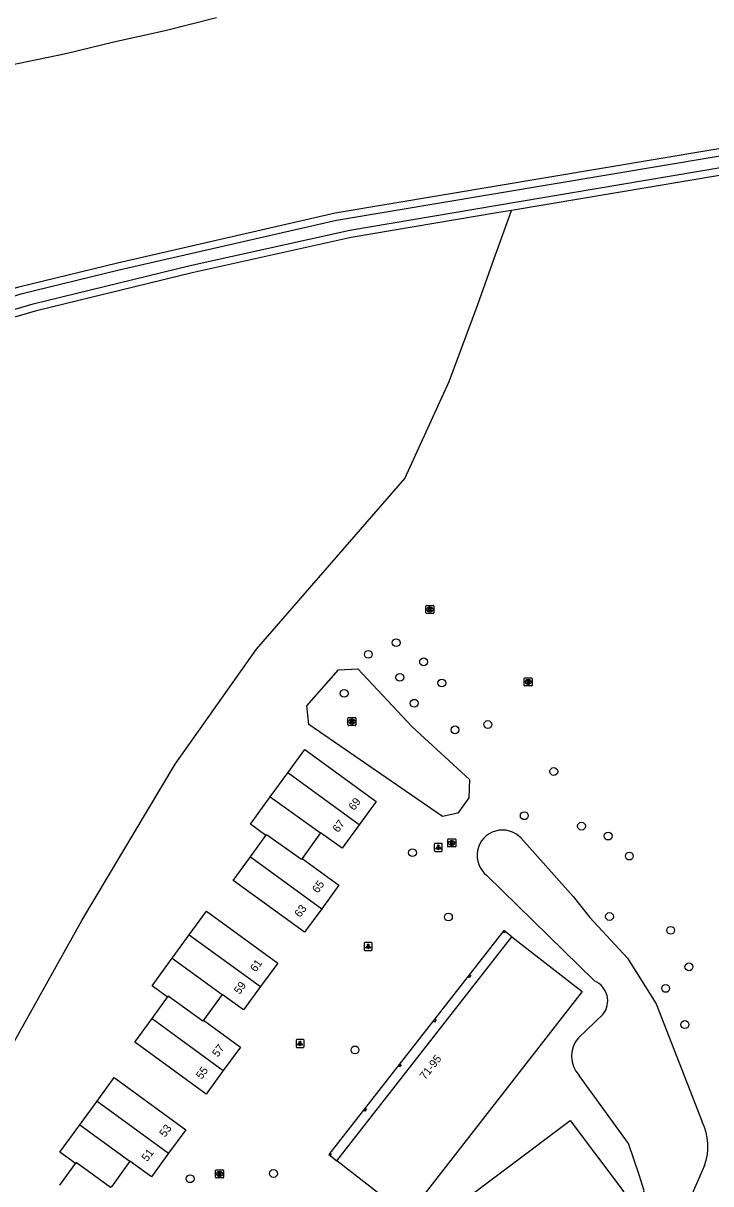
# Model space of a CAD drawing. Extents: x 159451 to 160663, y 388402 to 389723.
# Drawn here: x 159537.5 to 159623.4, y 389378.7 to 389523.7 of the extents above; entities that cross this region are included whole.
import ezdxf

# ---------------------------------------------------------------- set-up
doc = ezdxf.new("R2010")
doc.units = 0
for name, color, linetype in [('IMGEO_Boom', 7, 'Continuous'), ('IMGEO_Greppel_droge_sloot', 7, 'Continuous'), ('IMGEO_Groenvoorziening', 7, 'Continuous'), ('IMGEO_Lichtpunt', 7, 'Continuous'), ('IMGEO_Loofbos', 7, 'Continuous'), ('IMGEO_Meer_plas_ven_vijver', 7, 'Continuous'), ('IMGEO_Pand', 7, 'Continuous'), ('IMGEO_Pand_nummerreeks', 7, 'Continuous'), ('IMGEO_Pand_overbouw', 7, 'Continuous'), ('IMGEO_Rioolput', 7, 'Continuous')]:
    doc.layers.add(name, color=color, linetype=linetype)

msp = doc.modelspace()

# ---------------------------------------------------------------- linework, layer by layer
at = {"layer": 'IMGEO_Boom'}
for centre in [(159584.08, 389446.29), (159580.61, 389444.83), (159587.51, 389443.9), (159584.54, 389441.96), (159589.79, 389441.25), (159577.59, 389439.96), (159586.34, 389438.72), (159591.44, 389435.4), (159595.54, 389436.07), (159603.78, 389430.19), (159600.09, 389424.66), (159607.24, 389423.36), (159610.57, 389422.12), (159586.12, 389420.04), (159613.22, 389419.62), (159590.61, 389412), (159610.74, 389412.07), (159618.38, 389410.34), (159620.66, 389405.78), (159617.76, 389403.08), (159620.16, 389398.56), (159578.94, 389395.39), (159558.34, 389379.29), (159568.76, 389379.94)]:
    msp.add_circle(centre, 0.489, dxfattribs=at)
at = {"layer": 'IMGEO_Greppel_droge_sloot'}
for points in [[(159636.97, 389509.2), (159576.64, 389499.06), (159549.47, 389492.85), (159537.2, 389489.84), (159529.84, 389487.62), (159524.73, 389485.71), (159521.07, 389483.56), (159517.26, 389480.74), (159512.48, 389476.42), (159508.93, 389471.27), (159507.1, 389466.58), (159505.63, 389461.3), (159504.52, 389456.13), (159503.66, 389450.55), (159500.95, 389426.85), (159489.57, 389330.45)], [(159490.64, 389330.24), (159499.05, 389400.46), (159504.98, 389451.19), (159506.87, 389461.63), (159508.71, 389466.85), (159510.07, 389470.22), (159513.86, 389475.84), (159519.24, 389480.5), (159524.71, 389483.94), (159529.91, 389486.08), (159538.73, 389488.65), (159558.36, 389493.45), (159578.28, 389497.87), (159596.51, 389500.94), (159637.44, 389507.84)]]:
    msp.add_lwpolyline(points, dxfattribs=at)
at = {"layer": 'IMGEO_Groenvoorziening'}
msp.add_lwpolyline([(159688.02, 389515.39), (159637.6, 389506.89), (159598.51, 389500.31)], dxfattribs=at)
at = {"layer": 'IMGEO_Lichtpunt'}
for p, q in [((159589.75, 389421.21), (159588.95, 389421.21)), ((159589.75, 389421.21), (159588.95, 389421.21)), ((159588.85, 389421.11), (159588.85, 389420.3)), ((159588.85, 389421.11), (159588.85, 389420.3)), ((159588.95, 389420.21), (159589.75, 389420.21)), ((159588.95, 389420.21), (159589.75, 389420.21)), ((159589.85, 389420.3), (159589.85, 389421.11)), ((159589.85, 389420.3), (159589.85, 389421.11)), ((159580.09, 389408.72), (159580.09, 389407.91)), ((159580.09, 389408.72), (159580.09, 389407.91)), ((159580.99, 389408.81), (159580.19, 389408.81)), ((159580.99, 389408.81), (159580.19, 389408.81)), ((159581.09, 389407.91), (159581.09, 389408.72)), ((159581.09, 389407.91), (159581.09, 389408.72)), ((159580.19, 389407.82), (159580.99, 389407.82)), ((159580.19, 389407.82), (159580.99, 389407.82)), ((159571.58, 389396.6), (159571.58, 389395.8)), ((159571.58, 389396.6), (159571.58, 389395.8)), ((159572.49, 389396.7), (159571.68, 389396.7)), ((159572.49, 389396.7), (159571.68, 389396.7)), ((159572.58, 389395.8), (159572.58, 389396.6)), ((159572.58, 389395.8), (159572.58, 389396.6)), ((159571.68, 389395.7), (159572.49, 389395.7)), ((159571.68, 389395.7), (159572.49, 389395.7))]:
    msp.add_line(p, q, dxfattribs=at)
for points in [[(159589.23, 389420.77), (159589.27, 389420.75), (159589.08, 389420.48), (159589.04, 389420.51), (159589.23, 389420.77)], [(159589.33, 389420.73), (159589.38, 389420.73), (159589.38, 389420.4), (159589.33, 389420.4), (159589.33, 389420.73)], [(159589.44, 389420.75), (159589.48, 389420.77), (159589.66, 389420.51), (159589.63, 389420.48), (159589.44, 389420.75)], [(159580.47, 389408.38), (159580.51, 389408.35), (159580.32, 389408.09), (159580.28, 389408.12), (159580.47, 389408.38)], [(159580.57, 389408.33), (159580.62, 389408.33), (159580.62, 389408.01), (159580.57, 389408.01), (159580.57, 389408.33)], [(159580.68, 389408.35), (159580.72, 389408.38), (159580.9, 389408.12), (159580.87, 389408.09), (159580.68, 389408.35)], [(159571.96, 389396.27), (159572, 389396.24), (159571.81, 389395.98), (159571.77, 389396.01), (159571.96, 389396.27)], [(159572.06, 389396.22), (159572.11, 389396.22), (159572.11, 389395.9), (159572.06, 389395.9), (159572.06, 389396.22)], [(159572.17, 389396.24), (159572.21, 389396.27), (159572.4, 389396), (159572.36, 389395.98), (159572.17, 389396.24)]]:
    msp.add_lwpolyline(points, dxfattribs=at)
for centre in [(159589.35, 389420.91), (159580.59, 389408.52), (159572.08, 389396.4)]:
    msp.add_circle(centre, 0.0994, dxfattribs=at)
for centre, start, end in [((159588.95, 389421.11), 90, 180), ((159588.95, 389421.11), 90, 180), ((159589.75, 389421.11), 0, 90), ((159589.75, 389421.11), 0, 90), ((159588.95, 389420.3), 180, 270), ((159588.95, 389420.3), 180, 270), ((159589.75, 389420.3), 270, 0), ((159589.75, 389420.3), 270, 360), ((159580.19, 389408.72), 90, 180), ((159580.19, 389408.72), 90, 180), ((159580.99, 389408.72), 0, 90), ((159580.99, 389408.72), 0, 90), ((159580.19, 389407.91), 180, 270), ((159580.19, 389407.91), 180, 270), ((159580.99, 389407.91), 270, 0), ((159580.99, 389407.91), 270, 360), ((159571.68, 389396.6), 90, 180), ((159571.68, 389396.6), 90, 180), ((159572.49, 389396.6), 0, 90), ((159572.49, 389396.6), 0, 90), ((159571.68, 389395.8), 180, 270), ((159571.68, 389395.8), 180, 270), ((159572.49, 389395.8), 270, 0), ((159572.49, 389395.8), 270, 360)]:
    msp.add_arc(centre, 0.0946, start, end, dxfattribs=at)
at = {"layer": 'IMGEO_Loofbos'}
for points in [[(159561.64, 389524.37), (159555.24, 389522.78), (159548.8, 389521.36), (159542.8, 389519.87), (159528.48, 389516.92), (159521.04, 389515.55), (159515.21, 389514.3), (159510.41, 389513.47), (159505.2, 389512.43), (159499.7, 389511.56), (159495.02, 389511.51), (159491.43, 389510.98), (159486.3, 389511.71), (159481.7, 389512.58), (159478.26, 389513.99), (159474.39, 389514.86), (159469.54, 389515.51), (159467.54, 389516.53)], [(159488.62, 389330.56), (159500, 389426.96), (159502.71, 389450.67), (159503.58, 389456.3), (159504.7, 389461.53), (159506.19, 389466.88), (159508.08, 389471.72), (159511.76, 389477.05), (159516.65, 389481.48), (159520.54, 389484.36), (159524.32, 389486.57), (159529.53, 389488.52), (159536.95, 389490.76), (159549.25, 389493.78), (159576.46, 389500), (159636.81, 389510.14), (159699.07, 389520.6), (159714.9, 389522.58), (159722.51, 389523.32), (159725.62, 389523.47), (159729.75, 389522.51)], [(159485.81, 389295.21), (159491.99, 389308.12), (159504.18, 389336.44), (159514.87, 389357.94), (159544.81, 389411.57), (159556.46, 389431.12), (159566.64, 389445.47), (159585.18, 389466.83), (159590.7, 389478.95), (159594.28, 389488.58), (159596.13, 389493.71), (159598.51, 389500.31)], [(159598.51, 389500.31), (159596.67, 389500), (159578.46, 389496.93), (159558.58, 389492.52), (159538.98, 389487.72), (159530.23, 389485.17), (159525.15, 389483.08), (159519.81, 389479.73), (159514.58, 389475.2), (159510.92, 389469.77), (159509.61, 389466.52), (159507.8, 389461.38), (159505.93, 389451.05), (159500, 389400.35), (159491.59, 389330.09)]]:
    msp.add_lwpolyline(points, dxfattribs=at)
at = {"layer": 'IMGEO_Meer_plas_ven_vijver'}
for points in [[(159589.86, 389424.57), (159573.18, 389436.06), (159572.94, 389438.39), (159576.87, 389442.89), (159579.29, 389443.04), (159586.1, 389435.77), (159593.23, 389429.19), (159593.16, 389426.89), (159591.8, 389425), (159589.86, 389424.57)], [(159599.69, 389421.85), (159606.21, 389414.57), (159608.28, 389411.94), (159612.97, 389406.85), (159616.55, 389401.14), (159622.3, 389386.4)], [(159608.88, 389404.02), (159595.42, 389417.19)], [(159606.86, 389396.92), (159609.94, 389399.84)], [(159591.09, 389358.32), (159614.72, 389376.73), (159615.08, 389377.79), (159614.44, 389379.79), (159613.1, 389383.71), (159606.95, 389392.21)], [(159622.61, 389380.94), (159618.83, 389372.29)]]:
    msp.add_lwpolyline(points, dxfattribs=at)
for centre, radius, start, end in [((159597.36, 389419.7), 3.17, 42.4764, 232.4269), ((159607.78, 389401.52), 2.73, 322.1853, 66.2612), ((159609.5, 389394.61), 3.51, 138.9641, 223.3007), ((159616.21, 389383.31), 6.83, 339.6435, 26.8753)]:
    msp.add_arc(centre, radius, start, end, dxfattribs=at)
at = {"layer": 'IMGEO_Pand'}
for points in [[(159570.54, 389430.01), (159572.66, 389432.93), (159581.58, 389426.46), (159579.46, 389423.53)], [(159568.36, 389427.01), (159570.54, 389430.01)], [(159579.46, 389423.53), (159570.54, 389430.01)], [(159567.82, 389422.2), (159565.88, 389423.61), (159568.36, 389427.01)], [(159568.36, 389427.01), (159574.63, 389422.54)], [(159579.46, 389423.53), (159577.34, 389420.6), (159574.63, 389422.54)], [(159565.87, 389419.52), (159567.82, 389422.2)], [(159572.33, 389419.31), (159572.24, 389419.19), (159567.89, 389422.29), (159567.82, 389422.2)], [(159574.63, 389422.54), (159572.33, 389419.31)], [(159574.79, 389413.04), (159572.65, 389410.09), (159563.73, 389416.57), (159565.87, 389419.52)], [(159565.87, 389419.52), (159574.79, 389413.04)], [(159572.33, 389419.31), (159576.93, 389415.98), (159574.79, 389413.04)], [(159558.23, 389409.79), (159560.37, 389412.74), (159569.28, 389406.25), (159567.15, 389403.32)], [(159556.1, 389406.85), (159558.23, 389409.79)], [(159558.23, 389409.79), (159567.15, 389403.32)], [(159585.49, 389374.64), (159576.69, 389381.52), (159598.55, 389409.54), (159607.34, 389402.68), (159585.49, 389374.64)], [(159597.59, 389410.04), (159597.46, 389410.14), (159597.56, 389410.27), (159597.69, 389410.17), (159597.59, 389410.04)], [(159555.51, 389401.98), (159553.58, 389403.39), (159556.1, 389406.85)], [(159556.1, 389406.85), (159562.35, 389402.32)], [(159593.21, 389404.43), (159593.08, 389404.52), (159593.28, 389404.78), (159593.4, 389404.68), (159593.21, 389404.43)], [(159562.35, 389402.32), (159560.01, 389399.1)], [(159567.15, 389403.32), (159565.02, 389400.39), (159562.35, 389402.32)], [(159553.58, 389399.33), (159555.51, 389401.98)], [(159560.01, 389399.1), (159559.92, 389398.97), (159555.6, 389402.1), (159555.51, 389401.98)], [(159562.49, 389392.81), (159560.34, 389389.88), (159551.43, 389396.36), (159553.58, 389399.33)], [(159553.58, 389399.33), (159562.49, 389392.81)], [(159560.01, 389399.1), (159564.64, 389395.75), (159562.49, 389392.81)], [(159588.87, 389398.87), (159588.75, 389398.97), (159588.94, 389399.22), (159589.07, 389399.12), (159588.87, 389398.87)], [(159584.51, 389393.28), (159584.39, 389393.38), (159584.58, 389393.63), (159584.71, 389393.53), (159584.51, 389393.28)], [(159546.73, 389389), (159548.86, 389391.93), (159557.8, 389385.4), (159555.66, 389382.47)], [(159544.58, 389386.03), (159546.73, 389389)], [(159546.73, 389389), (159555.66, 389382.47)], [(159580.37, 389387.97), (159580.18, 389387.72), (159580.05, 389387.82), (159580.25, 389388.07), (159580.37, 389387.97)], [(159589.76, 389360.53), (159583.05, 389369.44), (159605.81, 389386.58), (159612.53, 389377.66), (159589.76, 389360.53)], [(159544.02, 389381.19), (159542.08, 389382.6), (159544.58, 389386.03)], [(159544.58, 389386.03), (159550.82, 389381.5)], [(159555.66, 389382.47), (159553.52, 389379.54), (159550.82, 389381.5)], [(159575.89, 389382.22), (159575.76, 389382.32), (159575.86, 389382.45), (159575.99, 389382.35), (159575.89, 389382.22)], [(159542.07, 389378.5), (159544.02, 389381.19)], [(159548.5, 389378.3), (159548.41, 389378.18), (159544.11, 389381.3), (159544.02, 389381.19)], [(159550.82, 389381.5), (159548.5, 389378.3)]]:
    msp.add_lwpolyline(points, dxfattribs=at)
at = {"layer": 'IMGEO_Pand_overbouw'}
msp.add_lwpolyline([(159598.55, 389409.54), (159597.53, 389410.33), (159575.67, 389382.31), (159576.69, 389381.52)], close=True, dxfattribs=at)
at = {"layer": 'IMGEO_Rioolput'}
for p, q in [((159587.8, 389450.02), (159587.8, 389450.87)), ((159587.87, 389450.94), (159588.72, 389450.94)), ((159588.28, 389450.72), (159588.31, 389450.72)), ((159588.31, 389450.16), (159588.28, 389450.16)), ((159588.8, 389450.87), (159588.8, 389450.02)), ((159588.72, 389449.94), (159587.87, 389449.94)), ((159600.08, 389440.96), (159600.08, 389441.81)), ((159600.15, 389441.89), (159601.01, 389441.89)), ((159600.57, 389441.67), (159600.59, 389441.67)), ((159601.08, 389441.81), (159601.08, 389440.96)), ((159601.01, 389440.89), (159600.15, 389440.89)), ((159600.59, 389441.11), (159600.56, 389441.11)), ((159578.06, 389436.01), (159578.06, 389436.86)), ((159578.13, 389436.94), (159578.98, 389436.94)), ((159578.98, 389435.94), (159578.13, 389435.94)), ((159578.54, 389436.72), (159578.57, 389436.72)), ((159578.57, 389436.16), (159578.54, 389436.16)), ((159579.06, 389436.86), (159579.06, 389436.01)), ((159590.53, 389420.83), (159590.53, 389421.68)), ((159590.6, 389421.76), (159591.45, 389421.76)), ((159591.02, 389421.54), (159591.04, 389421.54)), ((159591.53, 389421.68), (159591.53, 389420.83)), ((159591.45, 389420.76), (159590.6, 389420.76)), ((159591.04, 389420.98), (159591.01, 389420.98)), ((159561.52, 389379.47), (159561.52, 389380.32)), ((159561.59, 389380.4), (159562.44, 389380.4)), ((159562.44, 389379.4), (159561.59, 389379.4)), ((159562.03, 389379.62), (159562, 389379.62)), ((159562.01, 389380.18), (159562.03, 389380.18)), ((159562.52, 389380.32), (159562.52, 389379.47))]:
    msp.add_line(p, q, dxfattribs=at)
for points in [[(159587.8, 389450.02), (159587.8, 389450.87)], [(159587.87, 389450.94), (159588.72, 389450.94)], [(159588.39, 389450.64), (159588.13, 389450.64), (159588.13, 389450.24)], [(159588.13, 389450.24), (159588.26, 389450.24), (159588.26, 389450.4), (159588.27, 389450.4)], [(159588.31, 389450.56), (159588.26, 389450.56), (159588.26, 389450.48)], [(159588.26, 389450.48), (159588.31, 389450.48)], [(159588.31, 389450.37), (159588.39, 389450.24), (159588.53, 389450.24), (159588.46, 389450.37)], [(159588.8, 389450.87), (159588.8, 389450.02)], [(159588.72, 389449.94), (159587.87, 389449.94)], [(159600.08, 389440.96), (159600.08, 389441.81)], [(159600.15, 389441.89), (159601.01, 389441.89)], [(159600.67, 389441.59), (159600.42, 389441.59), (159600.42, 389441.19)], [(159600.59, 389441.51), (159600.54, 389441.51), (159600.54, 389441.43)], [(159600.54, 389441.43), (159600.59, 389441.43)], [(159601.08, 389441.81), (159601.08, 389440.96)], [(159601.01, 389440.89), (159600.15, 389440.89)], [(159600.42, 389441.19), (159600.54, 389441.19), (159600.54, 389441.35), (159600.55, 389441.35)], [(159600.6, 389441.32), (159600.67, 389441.19), (159600.81, 389441.19), (159600.74, 389441.31)], [(159578.06, 389436.01), (159578.06, 389436.86)], [(159578.13, 389436.94), (159578.98, 389436.94)], [(159578.98, 389435.94), (159578.13, 389435.94)], [(159578.65, 389436.63), (159578.39, 389436.64), (159578.39, 389436.24)], [(159578.39, 389436.24), (159578.52, 389436.24), (159578.52, 389436.4), (159578.53, 389436.4)], [(159578.57, 389436.56), (159578.52, 389436.56), (159578.52, 389436.47)], [(159578.52, 389436.47), (159578.57, 389436.47)], [(159578.57, 389436.37), (159578.65, 389436.24), (159578.79, 389436.24), (159578.72, 389436.36)], [(159579.06, 389436.86), (159579.06, 389436.01)], [(159590.53, 389420.83), (159590.53, 389421.68)], [(159590.6, 389421.76), (159591.45, 389421.76)], [(159591.12, 389421.45), (159590.86, 389421.46), (159590.86, 389421.06)], [(159590.86, 389421.06), (159590.99, 389421.06), (159590.99, 389421.22), (159591, 389421.22)], [(159591.04, 389421.38), (159590.99, 389421.38), (159590.99, 389421.29)], [(159590.99, 389421.29), (159591.04, 389421.29)], [(159591.05, 389421.19), (159591.12, 389421.06), (159591.26, 389421.06), (159591.19, 389421.18)], [(159591.53, 389421.68), (159591.53, 389420.83)], [(159591.45, 389420.76), (159590.6, 389420.76)], [(159561.52, 389379.47), (159561.52, 389380.32)], [(159561.59, 389380.4), (159562.44, 389380.4)], [(159562.44, 389379.4), (159561.59, 389379.4)], [(159562.11, 389380.09), (159561.85, 389380.1), (159561.85, 389379.7)], [(159561.85, 389379.7), (159561.98, 389379.7), (159561.98, 389379.86), (159561.99, 389379.86)], [(159562.03, 389380.02), (159561.98, 389380.02), (159561.98, 389379.93)], [(159561.98, 389379.93), (159562.03, 389379.93)], [(159562.04, 389379.83), (159562.11, 389379.7), (159562.25, 389379.7), (159562.18, 389379.82)], [(159562.52, 389380.32), (159562.52, 389379.47)]]:
    msp.add_lwpolyline(points, dxfattribs=at)
for centre, radius, start, end in [((159587.87, 389450.87), 0.0765, 91.552, 178.448), ((159587.87, 389450.87), 0.0765, 91.552, 178.448), ((159588.27, 389450.35), 0.0533, 26.0293, 88.6989), ((159588.32, 389450.46), 0.0964, 77.0061, 93.1865), ((159588.29, 389450.67), 0.19, 274.7715, 282.9687), ((159588.33, 389450.52), 0.0378, 276.6634, 79.6772), ((159588.38, 389450.53), 0.109, 350.3612, 89.416), ((159588.38, 389450.53), 0.112, 277.5842, 350.9817), ((159588.37, 389450.31), 0.108, 29.5134, 73.7905), ((159588.72, 389450.87), 0.0765, 1.552, 88.448), ((159588.72, 389450.87), 0.0765, 1.552, 88.448), ((159587.87, 389450.02), 0.0765, 181.552, 268.448), ((159587.87, 389450.02), 0.0765, 181.552, 268.448), ((159588.72, 389450.02), 0.0765, 271.552, 358.448), ((159588.72, 389450.02), 0.0765, 271.552, 358.448), ((159600.16, 389441.81), 0.0765, 91.552, 178.448), ((159600.16, 389441.81), 0.0765, 91.552, 178.448), ((159600.6, 389441.41), 0.0964, 77.0061, 93.1865), ((159600.58, 389441.62), 0.19, 274.7715, 282.9687), ((159600.61, 389441.47), 0.0378, 276.6634, 79.6772), ((159600.67, 389441.48), 0.109, 350.3612, 89.416), ((159600.67, 389441.48), 0.112, 277.5842, 350.9817), ((159601, 389441.81), 0.0765, 1.552, 88.448), ((159601, 389441.81), 0.0765, 1.552, 88.448), ((159600.16, 389440.96), 0.0765, 181.552, 268.448), ((159600.16, 389440.96), 0.0765, 181.552, 268.448), ((159600.55, 389441.3), 0.0533, 26.0293, 88.6989), ((159600.65, 389441.26), 0.108, 29.5134, 73.7905), ((159601, 389440.96), 0.0765, 271.552, 358.448), ((159601, 389440.96), 0.0765, 271.552, 358.448), ((159578.13, 389436.86), 0.0765, 91.552, 178.448), ((159578.13, 389436.86), 0.0765, 91.552, 178.448), ((159578.13, 389436.01), 0.0765, 181.552, 268.448), ((159578.13, 389436.01), 0.0765, 181.552, 268.448), ((159578.53, 389436.35), 0.0533, 26.0293, 88.6989), ((159578.58, 389436.46), 0.0964, 77.0061, 93.1865), ((159578.55, 389436.66), 0.19, 274.7715, 282.9687), ((159578.59, 389436.52), 0.0378, 276.6634, 79.6772), ((159578.64, 389436.52), 0.109, 350.3612, 89.416), ((159578.64, 389436.52), 0.112, 277.5842, 350.9817), ((159578.63, 389436.31), 0.108, 29.5134, 73.7905), ((159578.98, 389436.86), 0.0765, 1.552, 88.448), ((159578.98, 389436.86), 0.0765, 1.552, 88.448), ((159578.98, 389436.01), 0.0765, 271.552, 358.448), ((159578.98, 389436.01), 0.0765, 271.552, 358.448), ((159590.6, 389421.68), 0.0765, 91.552, 178.448), ((159590.6, 389421.68), 0.0765, 91.552, 178.448), ((159591, 389421.17), 0.0533, 26.0293, 88.6989), ((159591.05, 389421.28), 0.0964, 77.0061, 93.1865), ((159591.02, 389421.48), 0.19, 274.7715, 282.9687), ((159591.06, 389421.34), 0.0378, 276.6634, 79.6772), ((159591.12, 389421.35), 0.109, 350.3612, 89.416), ((159591.11, 389421.34), 0.112, 277.5842, 350.9817), ((159591.1, 389421.13), 0.108, 29.5134, 73.7905), ((159591.45, 389421.68), 0.0765, 1.552, 88.448), ((159591.45, 389421.68), 0.0765, 1.552, 88.448), ((159590.6, 389420.83), 0.0765, 181.552, 268.448), ((159590.6, 389420.83), 0.0765, 181.552, 268.448), ((159591.45, 389420.83), 0.0765, 271.552, 358.448), ((159591.45, 389420.83), 0.0765, 271.552, 358.448), ((159561.59, 389380.32), 0.0765, 91.552, 178.448), ((159561.59, 389380.32), 0.0765, 91.552, 178.448), ((159561.59, 389379.47), 0.0765, 181.552, 268.448), ((159561.59, 389379.47), 0.0765, 181.552, 268.448), ((159561.99, 389379.81), 0.0533, 26.0293, 88.6989), ((159562.04, 389379.92), 0.0964, 77.0061, 93.1865), ((159562.01, 389380.12), 0.19, 274.7715, 282.9687), ((159562.05, 389379.98), 0.0378, 276.6634, 79.6772), ((159562.11, 389379.99), 0.109, 350.3612, 89.416), ((159562.1, 389379.98), 0.112, 277.5842, 350.9817), ((159562.09, 389379.77), 0.108, 29.5134, 73.7905), ((159562.44, 389380.32), 0.0765, 1.552, 88.448), ((159562.44, 389380.32), 0.0765, 1.552, 88.448), ((159562.44, 389379.47), 0.0765, 271.552, 358.448), ((159562.44, 389379.47), 0.0765, 271.552, 358.448)]:
    msp.add_arc(centre, radius, start, end, dxfattribs=at)
for centre, major_axis, ratio, start_param, end_param in [((159588.28, 389450.44), (-0.387, 0.002), 0.722429, 4.712389, 7.853982), ((159588.31, 389450.44), (-0.39, 0.002), 0.717154, 1.570796, 4.712389), ((159600.57, 389441.39), (-0.387, 0.002), 0.722429, 4.712389, 7.853982), ((159600.59, 389441.39), (-0.39, 0.002), 0.717154, 1.570796, 4.712389), ((159578.54, 389436.44), (-0.387, 0.002), 0.722429, 4.712389, 7.853982), ((159578.57, 389436.44), (-0.39, 0.002), 0.717154, 1.570796, 4.712389), ((159591.01, 389421.26), (-0.387, 0.002), 0.722429, 4.712389, 7.853982), ((159591.04, 389421.26), (-0.39, 0.002), 0.717154, 1.570796, 4.712389), ((159562, 389379.9), (-0.387, 0.002), 0.722429, 4.712389, 7.853982), ((159562.03, 389379.9), (-0.39, 0.002), 0.717154, 1.570796, 4.712389)]:
    msp.add_ellipse(centre, major_axis=major_axis, ratio=ratio, start_param=start_param, end_param=end_param, dxfattribs=at)

# ---------------------------------------------------------------- texts
at = {"layer": 'IMGEO_Pand_nummerreeks'}
for s, rotation, p in [('69', 54.0242, (159578.85, 389425.24)), ('67', 54.0242, (159576.85, 389422.48)), ('65', 53.9784, (159574.3, 389414.91)), ('63', 53.9784, (159572.09, 389411.87)), ('61', 54.0528, (159566.55, 389405.05)), ('59', 54.0528, (159564.53, 389402.26)), ('57', 53.8007, (159561.81, 389394.42)), ('71-95', 52.0418, (159587.71, 389391.58)), ('55', 53.8007, (159559.78, 389391.64)), ('53', 53.8122, (159555.21, 389384.41)), ('51', 53.8122, (159552.99, 389381.36))]:
    msp.add_text(s, height=1, rotation=rotation, dxfattribs=at).set_placement(p)

doc.saveas('drawing.dxf')
